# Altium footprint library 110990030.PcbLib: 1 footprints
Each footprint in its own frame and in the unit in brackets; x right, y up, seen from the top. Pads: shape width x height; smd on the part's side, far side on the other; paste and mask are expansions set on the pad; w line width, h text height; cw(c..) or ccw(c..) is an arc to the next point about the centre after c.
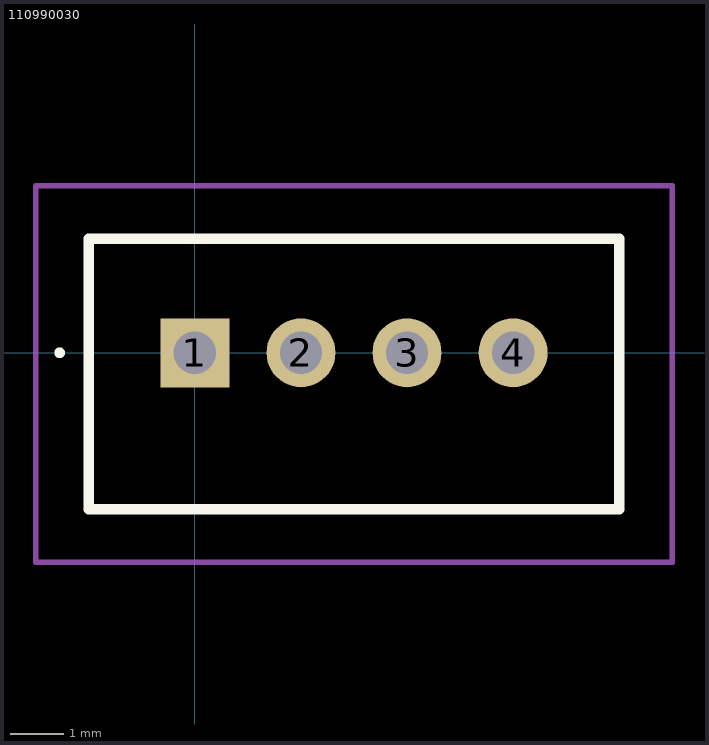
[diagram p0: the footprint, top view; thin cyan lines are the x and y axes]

## 110990030 [mm]
pads (4):
  rect 1.3x1.3 hole 0.8: 1(0,0)
  round 1.3 hole 0.8: 2(2,0) 3(4,0) 4(6,0)
Top Overlay:
  lines w0.1: -2.6,0 -2.6,0 ; -2.6,0 ccw(c-2.55,0) -2.5,0 ; -2.6,0 cw(c-2.55,0) -2.5,0 ; -2.5,0 -2.5,0
  lines w0.2: -2,-2.95 8,-2.95 8,2.15 -2,2.15 -2,-2.95
Mechanical 15:
  lines w0.1: -2,-2.95 8,-2.95 8,2.15 -2,2.15 -2,-2.95
Mechanical 20:
  lines w0.1: -3,-3.95 9,-3.95 9,3.15 -3,3.15 -3,-3.95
